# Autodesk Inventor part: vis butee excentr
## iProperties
Created: 2009-10
Part Number: vis butee excentr
Document SubType Name: Modeling
Designer: Olivier
Density: 1 g/cm^3
Author: Olivier
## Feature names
1. Extrusion1
2. Révolution1 [Revolution]
3. Extrusion2
4. Chanfrein1 [Chamfer]
